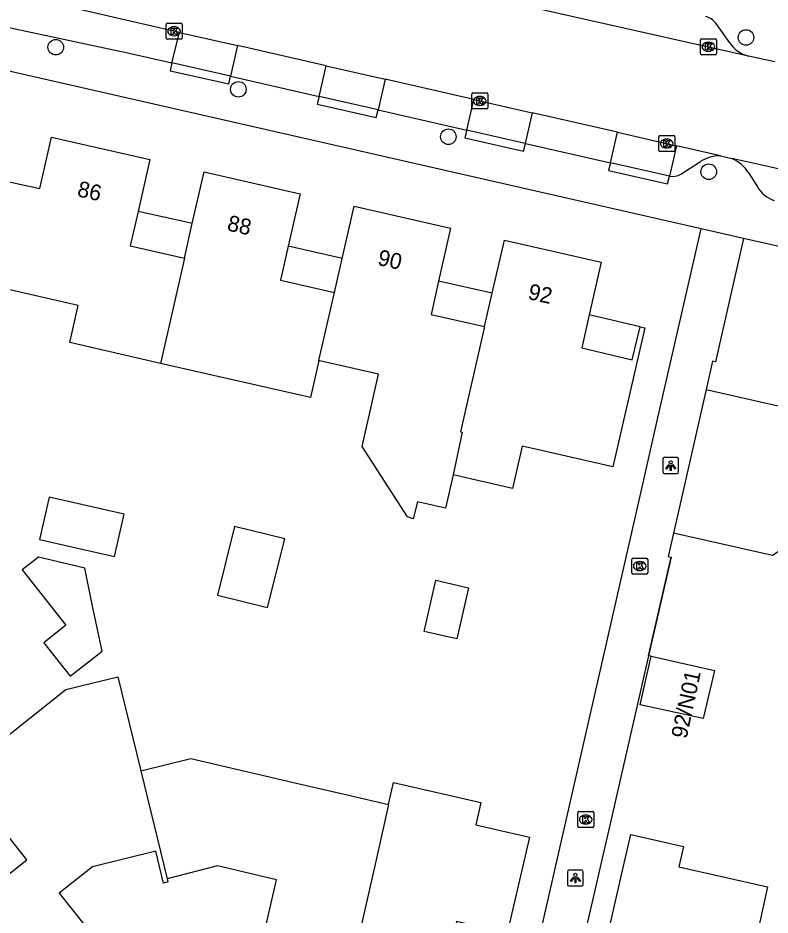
# Model space of a CAD drawing. Extents: x 159628 to 160723, y 388176 to 389416.
# Drawn here: x 160184.1 to 160231.4, y 388676.2 to 388732.7 of the extents above; entities that cross this region are included whole.
import ezdxf

# ---------------------------------------------------------------- set-up
doc = ezdxf.new("R2010")
doc.units = 0
for name, color, linetype in [('IMGEO_Boom', 7, 'Continuous'), ('IMGEO_Kolk', 7, 'Continuous'), ('IMGEO_Lichtpunt', 7, 'Continuous'), ('IMGEO_Muur', 7, 'Continuous'), ('IMGEO_Pand', 7, 'Continuous'), ('IMGEO_Pand_nummerreeks', 7, 'Continuous'), ('IMGEO_Pand_overbouw', 7, 'Continuous'), ('IMGEO_Parkeervlak_open', 7, 'Continuous'), ('IMGEO_Rijbaan_lokaal_gesloten', 7, 'Continuous'), ('IMGEO_Voetpad_open', 7, 'Continuous')]:
    doc.layers.add(name, color=color, linetype=linetype)

msp = doc.modelspace()

# ---------------------------------------------------------------- linework, layer by layer
at = {"layer": 'IMGEO_Boom'}
for centre in [(160229.904, 388731.42), (160186.449, 388730.81), (160197.945, 388728.157), (160211.166, 388725.17), (160227.558, 388722.969)]:
    msp.add_circle(centre, 0.489, dxfattribs=at)
at = {"layer": 'IMGEO_Kolk'}
for p, q in [((160193.399, 388731.387), (160193.399, 388732.239)), ((160193.474, 388732.313), (160194.326, 388732.313)), ((160193.887, 388732.093), (160193.912, 388732.093)), ((160194.4, 388732.239), (160194.4, 388731.387)), ((160194.326, 388731.313), (160193.474, 388731.313)), ((160193.91, 388731.533), (160193.885, 388731.533)), ((160227.039, 388730.408), (160227.039, 388731.26)), ((160227.114, 388731.334), (160227.966, 388731.334)), ((160228.04, 388731.26), (160228.04, 388730.408)), ((160227.527, 388731.114), (160227.552, 388731.114)), ((160227.966, 388730.334), (160227.114, 388730.334)), ((160227.55, 388730.554), (160227.525, 388730.554)), ((160212.717, 388727.927), (160213.569, 388727.927)), ((160212.642, 388727.001), (160212.642, 388727.853)), ((160213.13, 388727.707), (160213.155, 388727.707)), ((160213.643, 388727.853), (160213.643, 388727.001)), ((160213.569, 388726.927), (160212.717, 388726.927)), ((160213.153, 388727.147), (160213.128, 388727.147)), ((160224.414, 388724.317), (160224.414, 388725.169)), ((160224.489, 388725.243), (160225.341, 388725.243)), ((160225.415, 388725.169), (160225.415, 388724.317)), ((160224.902, 388725.023), (160224.927, 388725.023)), ((160225.341, 388724.243), (160224.489, 388724.243)), ((160224.925, 388724.463), (160224.9, 388724.463)), ((160222.713, 388697.715), (160222.713, 388698.567)), ((160222.788, 388698.641), (160223.64, 388698.641)), ((160223.714, 388698.567), (160223.714, 388697.715)), ((160223.201, 388698.421), (160223.226, 388698.421)), ((160223.64, 388697.641), (160222.788, 388697.641)), ((160223.224, 388697.861), (160223.199, 388697.861)), ((160219.389, 388682.686), (160220.241, 388682.686)), ((160219.314, 388681.76), (160219.314, 388682.612)), ((160219.802, 388682.466), (160219.827, 388682.466)), ((160220.315, 388682.612), (160220.315, 388681.76)), ((160220.241, 388681.686), (160219.389, 388681.686)), ((160219.825, 388681.906), (160219.8, 388681.906))]:
    msp.add_line(p, q, dxfattribs=at)
for points in [[(160193.399, 388731.387), (160193.399, 388732.239)], [(160193.474, 388732.313), (160194.326, 388732.313)], [(160193.72, 388732.013), (160193.843, 388732.013), (160193.843, 388731.862), (160193.973, 388732.013), (160194.137, 388732.013), (160193.991, 388731.862), (160194.144, 388731.613), (160193.992, 388731.613), (160193.907, 388731.777), (160193.843, 388731.71), (160193.843, 388731.613), (160193.72, 388731.613), (160193.72, 388732.013)], [(160194.4, 388732.239), (160194.4, 388731.387)], [(160194.326, 388731.313), (160193.474, 388731.313)], [(160227.039, 388730.408), (160227.039, 388731.26)], [(160227.114, 388731.334), (160227.966, 388731.334)], [(160228.04, 388731.26), (160228.04, 388730.408)], [(160227.36, 388731.034), (160227.483, 388731.034), (160227.483, 388730.883), (160227.613, 388731.034), (160227.777, 388731.034), (160227.631, 388730.883), (160227.784, 388730.634), (160227.632, 388730.634), (160227.547, 388730.798), (160227.483, 388730.731), (160227.483, 388730.634), (160227.36, 388730.634), (160227.36, 388731.034)], [(160227.966, 388730.334), (160227.114, 388730.334)], [(160212.717, 388727.927), (160213.569, 388727.927)], [(160212.642, 388727.001), (160212.642, 388727.853)], [(160212.963, 388727.627), (160213.086, 388727.627), (160213.086, 388727.476), (160213.216, 388727.627), (160213.38, 388727.627), (160213.234, 388727.476), (160213.387, 388727.227), (160213.235, 388727.227), (160213.15, 388727.391), (160213.086, 388727.324), (160213.086, 388727.227), (160212.963, 388727.227), (160212.963, 388727.627)], [(160213.643, 388727.853), (160213.643, 388727.001)], [(160213.569, 388726.927), (160212.717, 388726.927)], [(160224.414, 388724.317), (160224.414, 388725.169)], [(160224.489, 388725.243), (160225.341, 388725.243)], [(160225.415, 388725.169), (160225.415, 388724.317)], [(160224.735, 388724.943), (160224.858, 388724.943), (160224.858, 388724.792), (160224.988, 388724.943), (160225.152, 388724.943), (160225.006, 388724.792), (160225.159, 388724.543), (160225.007, 388724.543), (160224.922, 388724.707), (160224.858, 388724.64), (160224.858, 388724.543), (160224.735, 388724.543), (160224.735, 388724.943)], [(160225.341, 388724.243), (160224.489, 388724.243)], [(160222.713, 388697.715), (160222.713, 388698.567)], [(160222.788, 388698.641), (160223.64, 388698.641)], [(160223.714, 388698.567), (160223.714, 388697.715)], [(160223.034, 388698.341), (160223.157, 388698.341), (160223.157, 388698.19), (160223.287, 388698.341), (160223.451, 388698.341), (160223.305, 388698.19), (160223.458, 388697.941), (160223.306, 388697.941), (160223.221, 388698.105), (160223.157, 388698.038), (160223.157, 388697.941), (160223.034, 388697.941), (160223.034, 388698.341)], [(160223.64, 388697.641), (160222.788, 388697.641)], [(160219.389, 388682.686), (160220.241, 388682.686)], [(160219.314, 388681.76), (160219.314, 388682.612)], [(160219.635, 388682.386), (160219.758, 388682.386), (160219.758, 388682.235), (160219.888, 388682.386), (160220.052, 388682.386), (160219.906, 388682.235), (160220.059, 388681.986), (160219.907, 388681.986), (160219.822, 388682.15), (160219.758, 388682.083), (160219.758, 388681.986), (160219.635, 388681.986), (160219.635, 388682.386)], [(160220.315, 388682.612), (160220.315, 388681.76)], [(160220.241, 388681.686), (160219.389, 388681.686)]]:
    msp.add_lwpolyline(points, dxfattribs=at)
for centre, start, end in [((160193.476, 388732.237), 91.552, 178.448), ((160193.476, 388732.237), 91.552, 178.448), ((160194.324, 388732.237), 1.552, 88.448), ((160194.324, 388732.237), 1.552, 88.448), ((160193.476, 388731.389), 181.552, 268.448), ((160193.476, 388731.389), 181.552, 268.448), ((160194.324, 388731.389), 271.552, 358.448), ((160194.324, 388731.389), 271.552, 358.448), ((160227.116, 388731.258), 91.552, 178.448), ((160227.116, 388731.258), 91.552, 178.448), ((160227.964, 388731.258), 1.552, 88.448), ((160227.964, 388731.258), 1.552, 88.448), ((160227.116, 388730.41), 181.552, 268.448), ((160227.116, 388730.41), 181.552, 268.448), ((160227.964, 388730.41), 271.552, 358.448), ((160227.964, 388730.41), 271.552, 358.448), ((160212.719, 388727.851), 91.552, 178.448), ((160212.719, 388727.851), 91.552, 178.448), ((160213.567, 388727.851), 1.552, 88.448), ((160213.567, 388727.851), 1.552, 88.448), ((160212.719, 388727.003), 181.552, 268.448), ((160212.719, 388727.003), 181.552, 268.448), ((160213.567, 388727.003), 271.552, 358.448), ((160213.567, 388727.003), 271.552, 358.448), ((160224.491, 388725.167), 91.552, 178.448), ((160224.491, 388725.167), 91.552, 178.448), ((160225.339, 388725.167), 1.552, 88.448), ((160225.339, 388725.167), 1.552, 88.448), ((160224.491, 388724.319), 181.552, 268.448), ((160224.491, 388724.319), 181.552, 268.448), ((160225.339, 388724.319), 271.552, 358.448), ((160225.339, 388724.319), 271.552, 358.448), ((160222.79, 388698.565), 91.552, 178.448), ((160222.79, 388698.565), 91.552, 178.448), ((160223.638, 388698.565), 1.552, 88.448), ((160223.638, 388698.565), 1.552, 88.448), ((160222.79, 388697.717), 181.552, 268.448), ((160222.79, 388697.717), 181.552, 268.448), ((160223.638, 388697.717), 271.552, 358.448), ((160223.638, 388697.717), 271.552, 358.448), ((160219.391, 388682.61), 91.552, 178.448), ((160219.391, 388682.61), 91.552, 178.448), ((160220.239, 388682.61), 1.552, 88.448), ((160220.239, 388682.61), 1.552, 88.448), ((160219.391, 388681.762), 181.552, 268.448), ((160219.391, 388681.762), 181.552, 268.448), ((160220.239, 388681.762), 271.552, 358.448), ((160220.239, 388681.762), 271.552, 358.448)]:
    msp.add_arc(centre, 0.0765, start, end, dxfattribs=at)
for centre, major_axis, ratio, start_param, end_param in [((160193.886, 388731.813), (-0.387, 0.002), 0.722429, 4.712389, 7.853982), ((160193.911, 388731.813), (-0.39, 0.002), 0.717154, 1.570796, 4.712389), ((160227.526, 388730.834), (-0.387, 0.002), 0.722429, 4.712389, 7.853982), ((160227.551, 388730.834), (-0.39, 0.002), 0.717154, 1.570796, 4.712389), ((160213.129, 388727.427), (-0.387, 0.002), 0.722429, 4.712389, 7.853982), ((160213.154, 388727.427), (-0.39, 0.002), 0.717154, 1.570796, 4.712389), ((160224.901, 388724.743), (-0.387, 0.002), 0.722429, 4.712389, 7.853982), ((160224.926, 388724.743), (-0.39, 0.002), 0.717154, 1.570796, 4.712389), ((160223.2, 388698.141), (-0.387, 0.002), 0.722429, 4.712389, 7.853982), ((160223.225, 388698.141), (-0.39, 0.002), 0.717154, 1.570796, 4.712389), ((160219.801, 388682.186), (-0.387, 0.002), 0.722429, 4.712389, 7.853982), ((160219.826, 388682.186), (-0.39, 0.002), 0.717154, 1.570796, 4.712389)]:
    msp.add_ellipse(centre, major_axis=major_axis, ratio=ratio, start_param=start_param, end_param=end_param, dxfattribs=at)
at = {"layer": 'IMGEO_Lichtpunt'}
for p, q in [((160224.664, 388704.875), (160224.664, 388704.068)), ((160224.664, 388704.875), (160224.664, 388704.068)), ((160225.566, 388704.97), (160224.758, 388704.97)), ((160225.566, 388704.97), (160224.758, 388704.97)), ((160225.66, 388704.068), (160225.66, 388704.875)), ((160225.66, 388704.068), (160225.66, 388704.875)), ((160224.758, 388703.974), (160225.566, 388703.974)), ((160224.758, 388703.974), (160225.566, 388703.974)), ((160218.665, 388678.904), (160218.665, 388678.097)), ((160218.665, 388678.904), (160218.665, 388678.097)), ((160219.567, 388678.999), (160218.759, 388678.999)), ((160219.567, 388678.999), (160218.759, 388678.999)), ((160219.661, 388678.097), (160219.661, 388678.904)), ((160219.661, 388678.097), (160219.661, 388678.904)), ((160218.759, 388678.003), (160219.567, 388678.003)), ((160218.759, 388678.003), (160219.567, 388678.003))]:
    msp.add_line(p, q, dxfattribs=at)
for points in [[(160225.038, 388704.539), (160225.077, 388704.511), (160224.889, 388704.249), (160224.851, 388704.276), (160225.038, 388704.539)], [(160225.14, 388704.491), (160225.187, 388704.491), (160225.187, 388704.169), (160225.14, 388704.169), (160225.14, 388704.491)], [(160225.25, 388704.511), (160225.288, 388704.538), (160225.475, 388704.276), (160225.436, 388704.248), (160225.25, 388704.511)], [(160219.039, 388678.568), (160219.078, 388678.54), (160218.89, 388678.278), (160218.852, 388678.305), (160219.039, 388678.568)], [(160219.141, 388678.52), (160219.188, 388678.52), (160219.188, 388678.198), (160219.141, 388678.198), (160219.141, 388678.52)], [(160219.251, 388678.54), (160219.289, 388678.567), (160219.476, 388678.305), (160219.437, 388678.277), (160219.251, 388678.54)]]:
    msp.add_lwpolyline(points, dxfattribs=at)
for centre in [(160225.163, 388704.673), (160219.164, 388678.702)]:
    msp.add_circle(centre, 0.0994, dxfattribs=at)
for centre, start, end in [((160224.758, 388704.875), 90, 180), ((160224.758, 388704.875), 90, 180), ((160225.566, 388704.875), 0, 90), ((160225.566, 388704.875), 0, 90), ((160224.758, 388704.068), 180, 270), ((160224.758, 388704.068), 180, 270), ((160225.566, 388704.068), 270, 0), ((160225.566, 388704.068), 270, 360), ((160218.759, 388678.904), 90, 180), ((160218.759, 388678.904), 90, 180), ((160219.567, 388678.904), 0, 90), ((160219.567, 388678.904), 0, 90), ((160218.759, 388678.097), 180, 270), ((160218.759, 388678.097), 180, 270), ((160219.567, 388678.097), 270, 0), ((160219.567, 388678.097), 270, 360)]:
    msp.add_arc(centre, 0.0946, start, end, dxfattribs=at)
at = {"layer": 'IMGEO_Muur'}
for points in [[(160223.367, 388703.114), (160224.3, 388707.209)], [(160216.868, 388674.586), (160223.367, 388703.114)], [(160223.772, 388692.499), (160225.194, 388698.701)], [(160223.929, 388692.471), (160223.772, 388692.499)], [(160221.263, 388681.555), (160219.408, 388673.465)]]:
    msp.add_lwpolyline(points, dxfattribs=at)
at = {"layer": 'IMGEO_Pand'}
for points in [[(160179.715, 388723.147), (160185.44, 388721.912), (160186.192, 388725.152), (160192.371, 388723.746), (160191.631, 388720.475), (160191.14, 388718.305), (160194.551, 388717.534)], [(160194.551, 388717.534), (160195.043, 388719.703), (160195.784, 388722.971), (160201.834, 388721.584), (160201.086, 388718.276), (160200.601, 388716.134), (160203.99, 388715.368)], [(160203.99, 388715.368), (160204.479, 388717.507), (160205.232, 388720.803), (160211.309, 388719.424), (160210.553, 388716.084), (160210.078, 388713.984), (160213.45, 388713.222)], [(160213.45, 388713.222), (160213.931, 388715.318), (160214.697, 388718.656), (160220.785, 388717.266), (160220.025, 388713.963), (160219.569, 388711.883), (160222.739, 388711.12), (160223.244, 388713.208), (160223.525, 388713.137), (160221.525, 388704.392), (160216.651, 388705.507), (160215.813, 388705.698), (160215.202, 388703.03), (160211.459, 388703.887)], [(160194.551, 388717.534), (160193.047, 388710.904)], [(160193.047, 388710.904), (160187.329, 388712.212), (160187.863, 388714.55), (160181.336, 388716.043)], [(160203.012, 388711.086), (160203.99, 388715.368)], [(160227.4, 388709.263), (160232.392, 388708.126), (160232.796, 388709.901), (160233.69, 388713.83), (160239.411, 388712.521)], [(160213.45, 388713.222), (160211.928, 388706.586), (160212.026, 388706.564), (160211.459, 388703.887)], [(160203.012, 388711.086), (160202.478, 388708.747), (160193.047, 388710.904)], [(160211.459, 388703.887), (160210.98, 388701.792), (160209.218, 388702.195), (160208.943, 388701.124), (160208.592, 388701.238), (160205.731, 388705.666), (160206.239, 388707.888), (160206.774, 388710.226), (160203.159, 388711.052), (160203.012, 388711.086)], [(160227.4, 388709.263), (160225.341, 388700.225)], [(160237.101, 388702.549), (160233.73, 388703.316), (160233.152, 388700.775), (160232.916, 388699.692), (160231.578, 388698.805), (160225.341, 388700.225)], [(160190.76, 388701.405), (160186.035, 388702.486), (160185.425, 388699.816), (160190.15, 388698.736), (160190.76, 388701.405)], [(160200.867, 388699.853), (160197.705, 388700.642), (160196.626, 388696.316), (160199.789, 388695.528), (160200.867, 388699.853)], [(160188.275, 388698.006), (160185.357, 388698.71), (160184.337, 388697.902), (160187.089, 388694.427), (160185.689, 388693.318), (160187.365, 388691.202), (160189.369, 388692.79), (160188.737, 388695.733), (160188.275, 388698.006)], [(160210.378, 388697.248), (160212.43, 388696.778), (160211.694, 388693.56), (160209.642, 388694.029), (160210.378, 388697.248)], [(160227.205, 388688.538), (160223.231, 388689.418), (160223.929, 388692.471), (160227.914, 388691.566), (160227.205, 388688.538)], [(160180.288, 388676.212), (160184.636, 388679.653), (160180.363, 388685.053), (160187.079, 388690.367), (160190.366, 388691.168), (160191.806, 388685.26)], [(160191.806, 388685.26), (160194.948, 388686.026), (160201.961, 388684.396), (160205.072, 388683.673), (160207.406, 388683.131)], [(160191.806, 388685.26), (160193.462, 388678.46)], [(160207.406, 388683.131), (160207.721, 388684.525), (160213.216, 388683.249), (160212.892, 388681.855), (160216.278, 388681.068), (160214.876, 388675.037), (160211.68, 388675.76), (160210.166, 388668.826), (160204.464, 388670.132)], [(160207.406, 388683.131), (160206.662, 388679.837), (160204.464, 388670.132)], [(160228.29, 388664.664), (160222.59, 388665.97), (160223.44, 388669.93), (160220.24, 388670.68), (160222.18, 388679.17), (160222.652, 388681.237), (160225.96, 388680.481), (160225.668, 388679.203), (160231.266, 388677.947), (160230.518, 388674.594)], [(160193.462, 388678.46), (160193.511, 388678.261), (160193.234, 388678.185), (160192.74, 388680.189), (160188.756, 388679.203), (160186.674, 388677.55), (160191.072, 388672.005), (160186.483, 388668.375)], [(160204.464, 388670.132), (160203.441, 388670.366), (160203.274, 388669.635), (160202.23, 388669.105), (160200.003, 388669.616), (160199.295, 388670.558), (160199.46, 388671.278), (160198.758, 388671.439), (160200.341, 388678.395), (160196.628, 388679.266), (160193.462, 388678.46)]]:
    msp.add_lwpolyline(points, dxfattribs=at)
at = {"layer": 'IMGEO_Pand_overbouw'}
for points in [[(160195.043, 388719.703), (160194.865, 388719.743), (160191.631, 388720.475), (160191.14, 388718.305), (160194.551, 388717.534)], [(160204.479, 388717.507), (160204.319, 388717.543), (160201.086, 388718.276), (160200.601, 388716.134), (160203.99, 388715.368)], [(160213.931, 388715.318), (160210.553, 388716.084), (160210.078, 388713.984), (160213.45, 388713.222)], [(160223.244, 388713.208), (160220.025, 388713.963), (160219.569, 388711.883), (160222.739, 388711.12)]]:
    msp.add_lwpolyline(points, close=True, dxfattribs=at)
at = {"layer": 'IMGEO_Parkeervlak_open'}
for points in [[(160193.754, 388729.817), (160194.236, 388731.738)], [(160197.887, 388730.906), (160197.447, 388728.98)], [(160203.025, 388727.71), (160203.464, 388729.635)], [(160207.181, 388728.788), (160206.742, 388726.865)], [(160212.324, 388725.595), (160212.768, 388727.514)], [(160216.45, 388726.674), (160216.011, 388724.754)], [(160221.37, 388723.533), (160221.807, 388725.453)], [(160225.52, 388724.606), (160225.081, 388722.687)]]:
    msp.add_lwpolyline(points, dxfattribs=at)
at = {"layer": 'IMGEO_Rijbaan_lokaal_gesloten'}
for points in [[(160230.065, 388730.247), (160211.28, 388734.481)], [(160194.236, 388731.738), (160186.385, 388733.53)], [(160194.236, 388731.738), (160197.887, 388730.906)], [(160203.464, 388729.635), (160197.887, 388730.906)], [(160231.719, 388729.878), (160230.065, 388730.247)], [(160203.464, 388729.635), (160207.181, 388728.788)], [(160212.768, 388727.514), (160207.181, 388728.788)], [(160212.768, 388727.514), (160216.45, 388726.674)], [(160221.807, 388725.453), (160216.45, 388726.674)], [(160221.807, 388725.453), (160225.52, 388724.606)], [(160228.297, 388723.973), (160225.52, 388724.606)], [(160228.297, 388723.973), (160229.021, 388723.807)], [(160247.241, 388719.647), (160231.462, 388723.248), (160229.021, 388723.807)]]:
    msp.add_lwpolyline(points, dxfattribs=at)
at = {"layer": 'IMGEO_Voetpad_open'}
for points in [[(160181.115, 388732.553), (160191.078, 388730.424), (160193.754, 388729.817)], [(160228.876, 388731.081), (160227.997, 388732.315)], [(160227.072, 388719.379), (160183.407, 388729.319), (160181.681, 388729.655), (160179.863, 388729.928)], [(160193.754, 388729.817), (160193.643, 388729.33), (160197.336, 388728.492), (160197.447, 388728.98)], [(160197.447, 388728.98), (160193.754, 388729.817)], [(160197.447, 388728.98), (160203.025, 388727.71)], [(160203.025, 388727.71), (160202.914, 388727.223), (160206.631, 388726.377), (160206.742, 388726.865)], [(160206.742, 388726.865), (160203.025, 388727.71)], [(160206.742, 388726.865), (160212.324, 388725.595)], [(160212.324, 388725.595), (160212.213, 388725.108), (160215.9, 388724.267), (160216.013, 388724.754)], [(160216.011, 388724.754), (160212.324, 388725.595)], [(160216.011, 388724.754), (160216.013, 388724.754)], [(160216.013, 388724.754), (160221.37, 388723.533)], [(160221.37, 388723.533), (160221.258, 388723.045), (160224.97, 388722.2), (160225.081, 388722.687)], [(160225.081, 388722.687), (160221.37, 388723.533)], [(160225.792, 388722.823), (160227.036, 388723.608)], [(160230.077, 388722.88), (160230.621, 388722.026)], [(160214.412, 388663.806), (160216.868, 388674.586), (160223.367, 388703.114), (160224.3, 388707.209), (160227.072, 388719.379)], [(160229.749, 388718.77), (160227.072, 388719.379)], [(160229.749, 388718.77), (160227.986, 388710.997), (160227.804, 388711.038), (160227.4, 388709.263)], [(160321.781, 388697.748), (160237.27, 388717.058), (160229.749, 388718.77)], [(160225.341, 388700.225), (160225.004, 388698.744), (160225.194, 388698.701), (160223.772, 388692.499), (160221.263, 388681.555), (160219.408, 388673.465), (160217.052, 388663.19)]]:
    msp.add_lwpolyline(points, dxfattribs=at)
for centre, radius, start, end in [((160227.109, 388731.687), 1.088, 35.2876, 77.373), ((160230.538, 388732.186), 1.996, 213.6201, 256.286), ((160228.267, 388721.716), 2.257, 89.2381, 123.0484), ((160228.052, 388721.638), 2.376, 31.523, 65.921), ((160225.256, 388723.698), 1.026, 260.1678, 301.4897), ((160232.191, 388722.878), 1.786, 208.4784, 253.4154)]:
    msp.add_arc(centre, radius, start, end, dxfattribs=at)

# ---------------------------------------------------------------- texts
at = {"layer": 'IMGEO_Pand_nummerreeks'}
for s, rotation, p in [('86', 347.1829, (160187.748, 388721.434)), ('88', 347.0913, (160197.184, 388719.285)), ('90', 347.2116, (160206.658, 388717.116)), ('92', 347.1428, (160216.125, 388714.965)), ('92/N01', 77.8598, (160226.159, 388687.235))]:
    msp.add_text(s, height=1, rotation=rotation, dxfattribs=at).set_placement(p)

doc.saveas('drawing.dxf')
